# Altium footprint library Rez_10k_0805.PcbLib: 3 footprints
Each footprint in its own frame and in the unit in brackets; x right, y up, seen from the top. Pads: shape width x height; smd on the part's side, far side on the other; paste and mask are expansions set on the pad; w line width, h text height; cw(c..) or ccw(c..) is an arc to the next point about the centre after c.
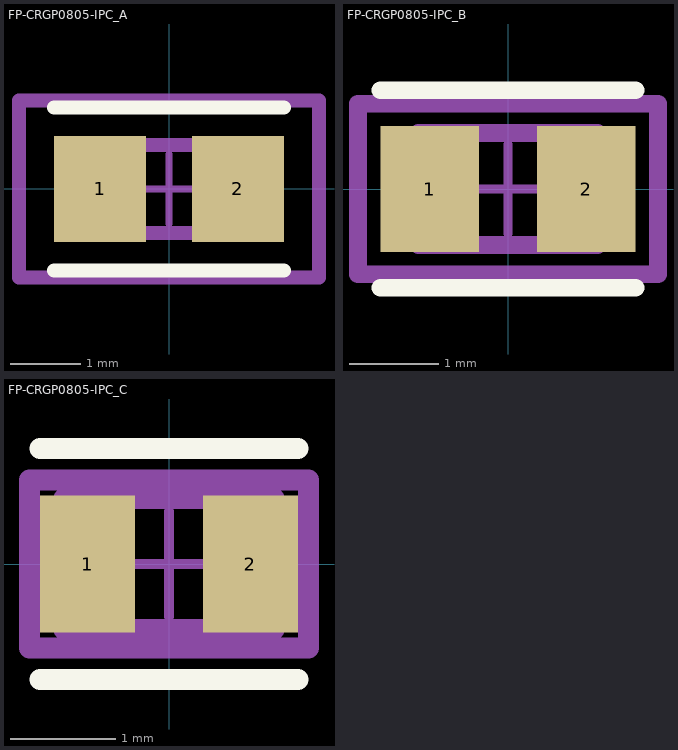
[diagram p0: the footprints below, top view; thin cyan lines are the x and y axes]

## FP-CRGP0805-IPC_A [mm]
pads (2):
  rect 1.306x1.51 smd paste+0 mask+0: 1(-0.976,0) 2(0.976,0)
Top Overlay:
  lines w0.2: -1.629,-1.155 1.629,-1.155 ; -1.629,1.155 1.629,1.155
Top Assembly:
  lines w0.2: -2.129,-1.255 2.129,-1.255 2.129,1.255 -2.129,1.255 -2.129,-1.255
  text ".Designator" at 0,0.188 h1
Top 3D Body:
  lines w0.2: -1,-0.625 1,-0.625 1,0.625 -1,0.625 -1,-0.625
Top Courtyard:
  lines w0.2: -2.129,-1.255 2.129,-1.255 2.129,1.255 -2.129,1.255 -2.129,-1.255
Top Component Center:
  lines w0.1: -0.5,0 0.5,0 ; 0,-0.5 0,0.5
3D body "Res_TE_CRGP0805F270K_eec.STEP": height 0.25, standoff 0, extent -2.129,-1.255 2.129,1.255

## FP-CRGP0805-IPC_B [mm]
pads (2):
  rect 1.106x1.41 smd paste+0 mask+0: 1(-0.876,0) 2(0.876,0)
Top Overlay:
  lines w0.2: -1.429,-1.105 1.429,-1.105 ; -1.429,1.105 1.429,1.105
Top Assembly:
  lines w0.2: -1.679,-0.955 1.679,-0.955 1.679,0.955 -1.679,0.955 -1.679,-0.955
  text ".Designator" at 0,0.188 h1
Top 3D Body:
  lines w0.2: -1,-0.625 1,-0.625 1,0.625 -1,0.625 -1,-0.625
Top Courtyard:
  lines w0.2: -1.679,-0.955 1.679,-0.955 1.679,0.955 -1.679,0.955 -1.679,-0.955
Top Component Center:
  lines w0.1: -0.5,0 0.5,0 ; 0,-0.5 0,0.5
3D body "Res_TE_CRGP0805F270K_eec.STEP": height 0.25, standoff 0, extent -1.679,-0.955 1.679,0.955

## FP-CRGP0805-IPC_C [mm]
pads (2):
  rect 0.906x1.31 smd paste+0 mask+0: 1(-0.776,0) 2(0.776,0)
Top Overlay:
  lines w0.2: -1.229,-1.1 1.229,-1.1 ; -1.229,1.1 1.229,1.1
Top Assembly:
  lines w0.2: -1.329,-0.8 1.329,-0.8 1.329,0.8 -1.329,0.8 -1.329,-0.8
  text ".Designator" at 0,0.188 h1
Top 3D Body:
  lines w0.2: -1,-0.625 1,-0.625 1,0.625 -1,0.625 -1,-0.625
Top Courtyard:
  lines w0.2: -1.329,-0.8 1.329,-0.8 1.329,0.8 -1.329,0.8 -1.329,-0.8
Top Component Center:
  lines w0.1: -0.5,0 0.5,0 ; 0,-0.5 0,0.5
3D body "Res_TE_CRGP0805F270K_eec.STEP": height 0.25, standoff 0, extent -1.329,-0.8 1.329,0.8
